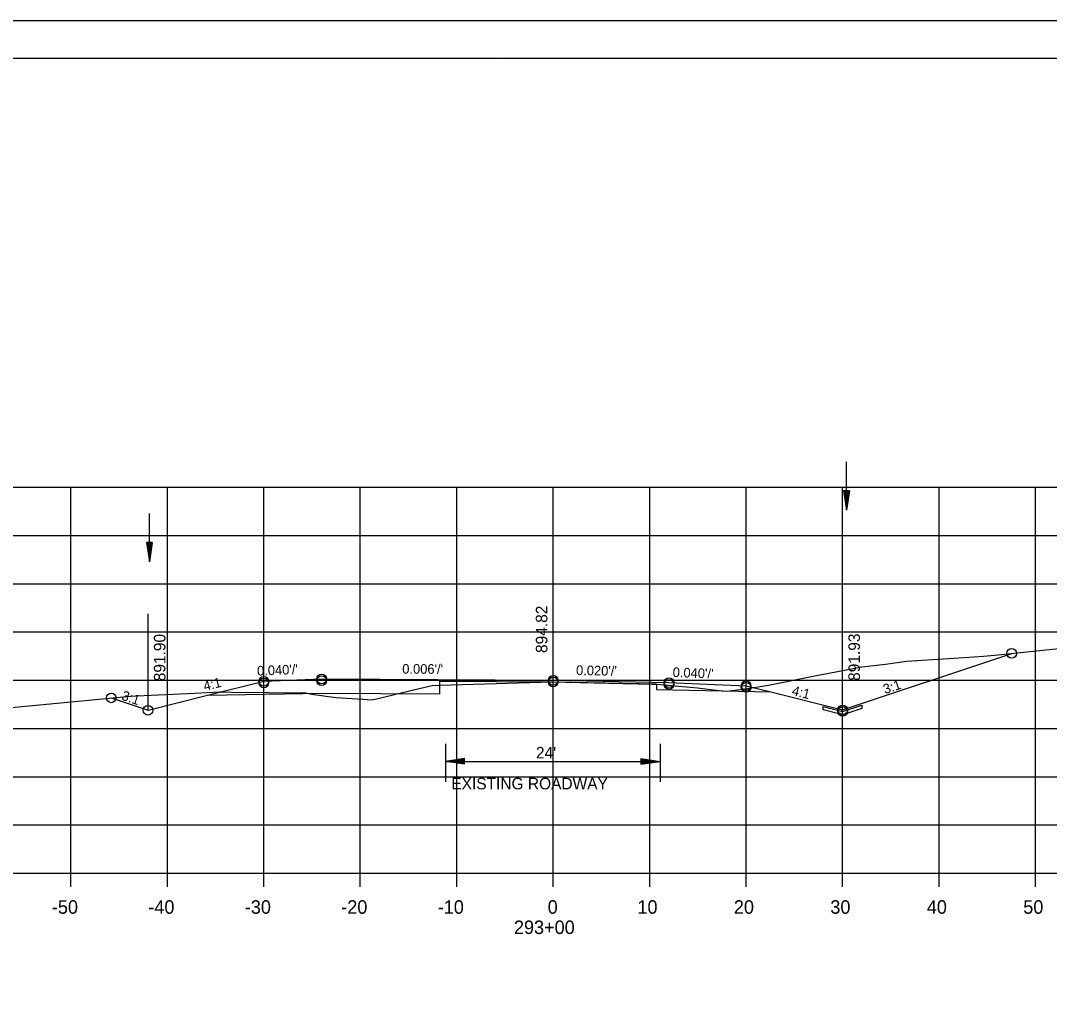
# Model space of a CAD drawing. Extents: x 1486524 to 1499135, y 326561 to 337924.
# Drawn here: x 1488927.7 to 1489034.3, y 333104.8 to 333206 of the extents above; entities that cross this region are included whole.
import ezdxf

# ---------------------------------------------------------------- set-up
doc = ezdxf.new("R2010")
doc.units = 0
for name, color, linetype in [('E_Const Align', 7, 'Continuous'), ('E_Const Align Station', 7, 'Continuous'), ('E_Ownership Information', 7, 'Continuous'), ('E_Property Line', 7, 'Continuous'), ('E_Proposed ROW and Easements', 7, 'Continuous'), ('E_Proposed ROW Fig Annot', 7, 'Continuous'), ('E_Quarter Calls', 7, 'Continuous'), ('E_Station Offset', 7, 'Continuous'), ('E_Survey Point', 7, 'Continuous'), ('E_Title Sheet', 7, 'Continuous'), ('E_Tract Number', 7, 'Continuous'), ('R_Water Annot', 7, 'Continuous'), ('R_Xsect Elev', 7, 'Continuous'), ('R_Xsect Slope', 7, 'Continuous')]:
    doc.layers.add(name, color=color, linetype=linetype)

msp = doc.modelspace()

# ---------------------------------------------------------------- linework, layer by layer
at = {"layer": 'E_Const Align'}
for p, q in [((1488842.89, 333117.63), (1489122.89, 333117.63)), ((1488932.89, 333116.23), (1488932.89, 333117.63)), ((1488942.89, 333116.23), (1488942.89, 333117.63)), ((1488952.89, 333116.23), (1488952.89, 333117.63)), ((1488962.89, 333116.23), (1488962.89, 333117.63)), ((1488972.89, 333116.23), (1488972.89, 333117.63)), ((1488982.89, 333116.23), (1488982.89, 333117.63)), ((1488992.89, 333116.23), (1488992.89, 333117.63)), ((1489002.89, 333116.23), (1489002.89, 333117.63)), ((1489012.89, 333116.23), (1489012.89, 333117.63)), ((1489022.89, 333116.23), (1489022.89, 333117.63)), ((1489032.89, 333116.23), (1489032.89, 333117.63))]:
    msp.add_line(p, q, dxfattribs=at)
at = {"layer": 'E_Ownership Information'}
for p, q in [((1488842.89, 333157.63), (1489122.89, 333157.63)), ((1488842.89, 333157.63), (1489122.89, 333157.63)), ((1488932.89, 333117.63), (1488932.89, 333157.63)), ((1488932.89, 333117.63), (1488932.89, 333157.63)), ((1488942.89, 333117.63), (1488942.89, 333157.63)), ((1488942.89, 333117.63), (1488942.89, 333157.63)), ((1488952.89, 333117.63), (1488952.89, 333157.63)), ((1488952.89, 333117.63), (1488952.89, 333157.63)), ((1488962.89, 333117.63), (1488962.89, 333157.63)), ((1488962.89, 333117.63), (1488962.89, 333157.63)), ((1488972.89, 333117.63), (1488972.89, 333157.63)), ((1488972.89, 333117.63), (1488972.89, 333157.63)), ((1488982.89, 333117.63), (1488982.89, 333157.63)), ((1488982.89, 333117.63), (1488982.89, 333157.63)), ((1488992.89, 333117.63), (1488992.89, 333157.63)), ((1488992.89, 333117.63), (1488992.89, 333157.63)), ((1489002.89, 333117.63), (1489002.89, 333157.63)), ((1489002.89, 333117.63), (1489002.89, 333157.63)), ((1489012.89, 333117.63), (1489012.89, 333157.63)), ((1489012.89, 333117.63), (1489012.89, 333157.63)), ((1489022.89, 333117.63), (1489022.89, 333157.63)), ((1489022.89, 333117.63), (1489022.89, 333157.63)), ((1489032.89, 333117.63), (1489032.89, 333157.63)), ((1489032.89, 333117.63), (1489032.89, 333157.63)), ((1488842.89, 333152.63), (1489122.89, 333152.63)), ((1488842.89, 333152.63), (1489122.89, 333152.63)), ((1488842.89, 333147.63), (1489122.89, 333147.63)), ((1488842.89, 333147.63), (1489122.89, 333147.63)), ((1488842.89, 333142.63), (1489122.89, 333142.63)), ((1488842.89, 333142.63), (1489122.89, 333142.63)), ((1488842.89, 333137.63), (1489122.89, 333137.63)), ((1488842.89, 333137.63), (1489122.89, 333137.63)), ((1488842.89, 333132.63), (1489122.89, 333132.63)), ((1488842.89, 333132.63), (1489122.89, 333132.63)), ((1488842.89, 333127.63), (1489122.89, 333127.63)), ((1488842.89, 333127.63), (1489122.89, 333127.63)), ((1488842.89, 333122.63), (1489122.89, 333122.63)), ((1488842.89, 333122.63), (1489122.89, 333122.63)), ((1488842.89, 333117.63), (1489122.89, 333117.63)), ((1488842.89, 333117.63), (1489122.89, 333117.63))]:
    msp.add_line(p, q, dxfattribs=at)
at = {"layer": 'E_Property Line'}
for p, q in [((1488824.89, 333202.09), (1489141.07, 333202.09)), ((1488977.41, 333201.83), (1488977.41, 333201.83)), ((1488977.41, 333201.83), (1488977.41, 333201.83))]:
    msp.add_line(p, q, dxfattribs=at)
at = {"layer": 'E_Proposed ROW and Easements'}
for p, q in [((1488971.71, 333131.03), (1488971.71, 333127.11)), ((1488993.99, 333131.03), (1488993.99, 333127.11)), ((1488973.71, 333129.52), (1488971.71, 333129.22)), ((1488973.71, 333128.92), (1488971.71, 333129.22)), ((1488973.71, 333129.47), (1488972.04, 333129.22)), ((1488973.71, 333128.97), (1488972.04, 333129.22)), ((1488973.71, 333129.42), (1488972.39, 333129.22)), ((1488973.71, 333129.02), (1488972.39, 333129.22)), ((1488973.71, 333129.37), (1488972.72, 333129.22)), ((1488973.71, 333129.07), (1488972.72, 333129.22)), ((1488973.71, 333129.31), (1488973.06, 333129.22)), ((1488973.71, 333129.12), (1488973.06, 333129.22)), ((1488973.71, 333129.26), (1488973.39, 333129.22)), ((1488973.71, 333129.17), (1488973.39, 333129.22)), ((1488973.71, 333128.92), (1488973.71, 333129.52)), ((1488991.99, 333129.52), (1488993.99, 333129.22)), ((1488991.99, 333129.52), (1488991.99, 333128.92)), ((1488991.99, 333129.47), (1488993.65, 333129.22)), ((1488991.99, 333129.42), (1488993.31, 333129.22)), ((1488991.99, 333129.37), (1488992.98, 333129.22)), ((1488991.99, 333129.32), (1488992.64, 333129.22)), ((1488991.99, 333129.27), (1488992.3, 333129.22)), ((1488991.99, 333128.92), (1488993.99, 333129.22)), ((1488991.99, 333129.12), (1488992.64, 333129.22)), ((1488991.99, 333129.02), (1488993.31, 333129.22)), ((1488991.99, 333128.97), (1488993.65, 333129.22)), ((1488991.99, 333129.07), (1488992.98, 333129.22)), ((1488991.99, 333129.17), (1488992.3, 333129.22))]:
    msp.add_line(p, q, dxfattribs=at)
at = {"layer": 'E_Proposed ROW Fig Annot'}
for p, q in [((1489013, 333157.25), (1489013.3, 333155.25)), ((1489013.6, 333157.25), (1489013, 333157.25)), ((1489013.05, 333157.25), (1489013.3, 333155.59)), ((1489013.1, 333157.25), (1489013.3, 333155.93)), ((1489013.15, 333157.25), (1489013.3, 333156.27)), ((1489013.2, 333157.25), (1489013.3, 333156.6)), ((1489013.25, 333157.25), (1489013.3, 333156.94)), ((1489013.6, 333157.25), (1489013.3, 333155.25)), ((1489013.4, 333157.25), (1489013.3, 333156.6)), ((1489013.5, 333157.25), (1489013.3, 333155.93)), ((1489013.55, 333157.25), (1489013.3, 333155.59)), ((1489013.45, 333157.25), (1489013.3, 333156.27)), ((1489013.35, 333157.25), (1489013.3, 333156.94)), ((1488940.73, 333151.91), (1488941.03, 333149.91)), ((1488941.33, 333151.91), (1488940.73, 333151.91)), ((1488940.78, 333151.91), (1488941.03, 333150.24)), ((1488940.83, 333151.91), (1488941.03, 333150.59)), ((1488940.88, 333151.91), (1488941.03, 333150.92)), ((1488940.93, 333151.91), (1488941.03, 333151.26)), ((1488940.98, 333151.91), (1488941.03, 333151.59)), ((1488941.33, 333151.91), (1488941.03, 333149.91)), ((1488941.12, 333151.91), (1488941.03, 333151.26)), ((1488941.23, 333151.91), (1488941.03, 333150.59)), ((1488941.28, 333151.91), (1488941.03, 333150.24)), ((1488941.18, 333151.91), (1488941.03, 333150.92)), ((1488941.07, 333151.91), (1488941.03, 333151.59)), ((1488971.71, 333129.22), (1488993.99, 333129.22))]:
    msp.add_line(p, q, dxfattribs=at)
at = {"layer": 'E_Quarter Calls'}
msp.add_line((1488812.48, 333205.98), (1489145.82, 333205.98), dxfattribs=at)
for points in [[(1488812.48, 333205.98), (1489145.82, 333205.98), (1489145.82, 332992.64), (1488812.48, 332992.64)], [(1489058.81, 333202.09), (1489058.81, 333192.21), (1489094.54, 333192.21), (1489094.54, 333189.29), (1489117.74, 333189.29), (1489117.74, 333164.95), (1489141.07, 333164.95), (1489141.07, 332996.63), (1488824.89, 332996.63), (1488824.89, 333202.09)]]:
    msp.add_lwpolyline(points, close=True, dxfattribs=at)
for centre in [(1489030.42, 333140.41), (1489030.42, 333140.41), (1488958.89, 333137.76), (1488958.89, 333137.76), (1488952.89, 333137.52), (1488952.89, 333137.52), (1488952.89, 333137.35), (1488958.89, 333137.59), (1488982.89, 333137.62), (1488982.89, 333137.62), (1488982.89, 333137.45), (1488994.89, 333137.38), (1488994.89, 333137.38), (1488994.89, 333137.21), (1489002.89, 333137.06), (1489002.89, 333137.06), (1489002.89, 333136.89), (1488937.07, 333135.8), (1488937.07, 333135.8), (1489012.89, 333134.56), (1489012.89, 333134.56), (1488940.89, 333134.52), (1488940.89, 333134.52), (1489012.89, 333134.39)]:
    msp.add_circle(centre, 0.5, dxfattribs=at)
at = {"layer": 'E_Station Offset'}
for p, q in [((1489012.89, 333134.39), (1489014.89, 333135.06)), ((1489014.89, 333135.06), (1489014.89, 333134.71)), ((1489010.87, 333134.89), (1489012.89, 333134.39)), ((1489010.87, 333134.55), (1489010.87, 333134.89)), ((1489012.9, 333134.04), (1489010.87, 333134.55)), ((1489014.89, 333134.71), (1489012.9, 333134.04))]:
    msp.add_line(p, q, dxfattribs=at)
at = {"layer": 'E_Survey Point'}
msp.add_lwpolyline([(1488947.06, 333136.07), (1488958.89, 333136.3), (1488971.15, 333136.23), (1488971.15, 333137.52), (1488982.89, 333137.45), (1488993.59, 333137.24), (1488993.6, 333136.66), (1489005.45, 333136.42)], dxfattribs=at)
at = {"layer": 'E_Title Sheet'}
msp.add_lwpolyline([(1488937.07, 333135.8), (1488940.89, 333134.52), (1488947.06, 333136.07), (1488952.89, 333137.52), (1488958.89, 333137.76), (1488982.89, 333137.62), (1488994.89, 333137.38), (1489002.89, 333137.06), (1489005.45, 333136.42), (1489012.89, 333134.56), (1489030.42, 333140.41)], dxfattribs=at)
at = {"layer": 'E_Tract Number'}
msp.add_lwpolyline([(1488915.84, 333133.78), (1488939.06, 333135.99), (1488939.72, 333136.02), (1488945.75, 333136.3), (1488948.31, 333136.42), (1488948.69, 333136.42), (1488949.56, 333136.4), (1488957.25, 333136.32), (1488957.87, 333136.2), (1488960.37, 333135.84), (1488963.17, 333135.65), (1488964.06, 333135.59), (1488964.76, 333135.74), (1488966.99, 333136.27), (1488969, 333136.77), (1488970.34, 333137.09), (1488971.06, 333137.12), (1488971.15, 333137.13), (1488981.65, 333137.42), (1488982.63, 333137.45), (1488993.14, 333137.22), (1488993.59, 333137.21), (1488994.53, 333137.15), (1488994.57, 333137.15), (1488994.78, 333137.13), (1488997.85, 333136.83), (1489000.08, 333136.58), (1489000.89, 333136.49), (1489003.02, 333136.78), (1489003.7, 333136.87), (1489005.2, 333137.1), (1489010.54, 333138.19), (1489011.45, 333138.37), (1489014.87, 333139.02), (1489017.34, 333139.28), (1489019.51, 333139.6), (1489025.5, 333140), (1489027.5, 333140.11), (1489029.01, 333140.26), (1489039.63, 333141.38)], dxfattribs=at)
at = {"layer": 'R_Water Annot'}
for p, q in [((1489013.3, 333155.25), (1489013.3, 333160.25)), ((1488941.03, 333149.91), (1488941.03, 333154.91))]:
    msp.add_line(p, q, dxfattribs=at)
at = {"layer": 'R_Xsect Elev'}
for p, q in [((1488982.89, 333137.45), (1488982.89, 333147.45)), ((1488940.89, 333134.52), (1488940.89, 333144.52)), ((1489012.89, 333134.56), (1489012.89, 333144.56))]:
    msp.add_line(p, q, dxfattribs=at)

# ---------------------------------------------------------------- texts
at = {"layer": 'E_Const Align Station'}
for s, p in [('-50', (1488930.92, 333113.43)), ('-40', (1488940.92, 333113.43)), ('-30', (1488950.92, 333113.43)), ('-20', (1488960.92, 333113.43)), ('-10', (1488970.92, 333113.43)), ('0', (1488982.32, 333113.43)), ('10', (1488991.62, 333113.43)), ('20', (1489001.62, 333113.43)), ('30', (1489011.62, 333113.43)), ('40', (1489021.62, 333113.43)), ('50', (1489031.62, 333113.43)), ('293+00', (1488978.82, 333111.33))]:
    msp.add_text(s, height=1.4, dxfattribs=at).set_placement(p)
at = {"layer": 'E_Proposed ROW Fig Annot'}
for s, p in [("24'", (1488981.1, 333129.52)), ('EXISTING ROADWAY', (1488972.33, 333126.32))]:
    msp.add_text(s, height=1.2, dxfattribs=at).set_placement(p)
at = {"layer": 'R_Xsect Elev'}
for s, p in [('894.82', (1488982.29, 333140.45)), ('891.90', (1488942.69, 333137.52)), ('891.93', (1489014.69, 333137.56))]:
    msp.add_text(s, height=1.2, rotation=90, dxfattribs=at).set_placement(p)
at = {"layer": 'R_Xsect Slope'}
for s, rotation, p in [("0.040'/'", 2.2906, (1488952.21, 333138.1)), ("0.006'/'", 359.6618, (1488967.24, 333138.31)), ("0.020'/'", 358.8542, (1488985.25, 333138.17)), ("0.040'/'", 357.7094, (1488995.26, 333137.97)), ('4:1', 14.0362, (1488946.76, 333136.51)), ('3:1', 18.4349, (1489017.29, 333136.18)), ('3:1', 341.5651, (1488938.07, 333135.63)), ('4:1', 345.9638, (1489007.57, 333136.11))]:
    msp.add_text(s, height=1, rotation=rotation, dxfattribs=at).set_placement(p)

doc.saveas('drawing.dxf')
